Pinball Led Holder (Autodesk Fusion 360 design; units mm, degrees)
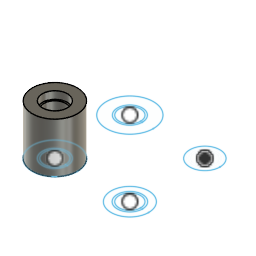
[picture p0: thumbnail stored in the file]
sketch "Sketch1" plane through (0, 0, 0) normal (0, 0, 1) x axis (1, 0, 0)
  circle C1 centre (0, 0) radius 2.85
  circle C2 centre (0, 0) radius 4
  circle C3 centre (0, 0) radius 3.35
  circle C4 centre (0, -20) radius 5
  circle C5 centre (0, -20) radius 3.35
  circle C6 centre (0, -20) radius 2.85
  circle C7 centre (-20, -20) radius 2.85
  circle C8 centre (-20, -20) radius 6
  circle C9 centre (-20, -20) radius 3.3
  circle C10 centre (-20, 0) radius 6.25
  circle C11 centre (-20, 0) radius 2.85
  circle C12 centre (-20, 0) radius 3.3
  point P1 (0, 0)
  point P2 (0, 0)
  coincident P1 P2
  concentric C1 C2
  concentric C1 C3
  concentric C4 C6
  concentric C5 C6
  concentric C7 C8
  concentric C7 C9
  concentric C10 C11
  concentric C11 C12
  dimension "d9" diameter C4 = 10
  dimension "d10" diameter C8 = 12
  dimension "d24" diameter C9 = 6.6
  dimension "d25" diameter C6 = 5.7
  dimension "d26" diameter C5 = 6.7
  dimension "d27" diameter C1 = 5.7
  dimension "d28" diameter C3 = 6.7
  dimension "d29" diameter C10 = 12.5
  dimension "d30" diameter C12 = 6.6
extrude "Extrude1" new body sketch "Sketch1" profile of C1 C2 C3 along normal blind 2.5 bodies "8mm"
extrude "Extrude2" add sketch "Sketch1" profile of C1 C3 along normal blind 11.3
extrude "Extrude3" add sketch "Sketch1" profile of C2 C3 along normal blind 13.3
fillet "Fillet1" radius 1.7
extrude "Extrude4" new body sketch "Sketch1" profile of C5 C6 along normal blind 11.3 bodies "10mm"
extrude "Extrude5" add sketch "Sketch1" profile of C4 C5 C6 along normal blind 2.5
extrude "Extrude6" add sketch "Sketch1" profile of C4 C5 along normal blind 13.3
extrude "Extrude7" new body sketch "Sketch1" profile of C7 C8 C9 along normal blind 2.5 bodies "12mm"
extrude "Extrude8" add sketch "Sketch1" profile of C7 C9 along normal blind 11.3
extrude "Extrude9" add sketch "Sketch1" profile of C8 C9 along normal blind 13.3
extrude "Extrude10" new body sketch "Sketch1" profile of C10 C12 along normal blind 13.3 bodies "12.5"
extrude "Extrude11" add sketch "Sketch1" profile of C11 C12 along normal blind 11.3
extrude "Extrude12" add sketch "Sketch1" profile of C11 along normal blind 1.5
named bodies: "8mm", "10mm", "12mm", "12.5"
